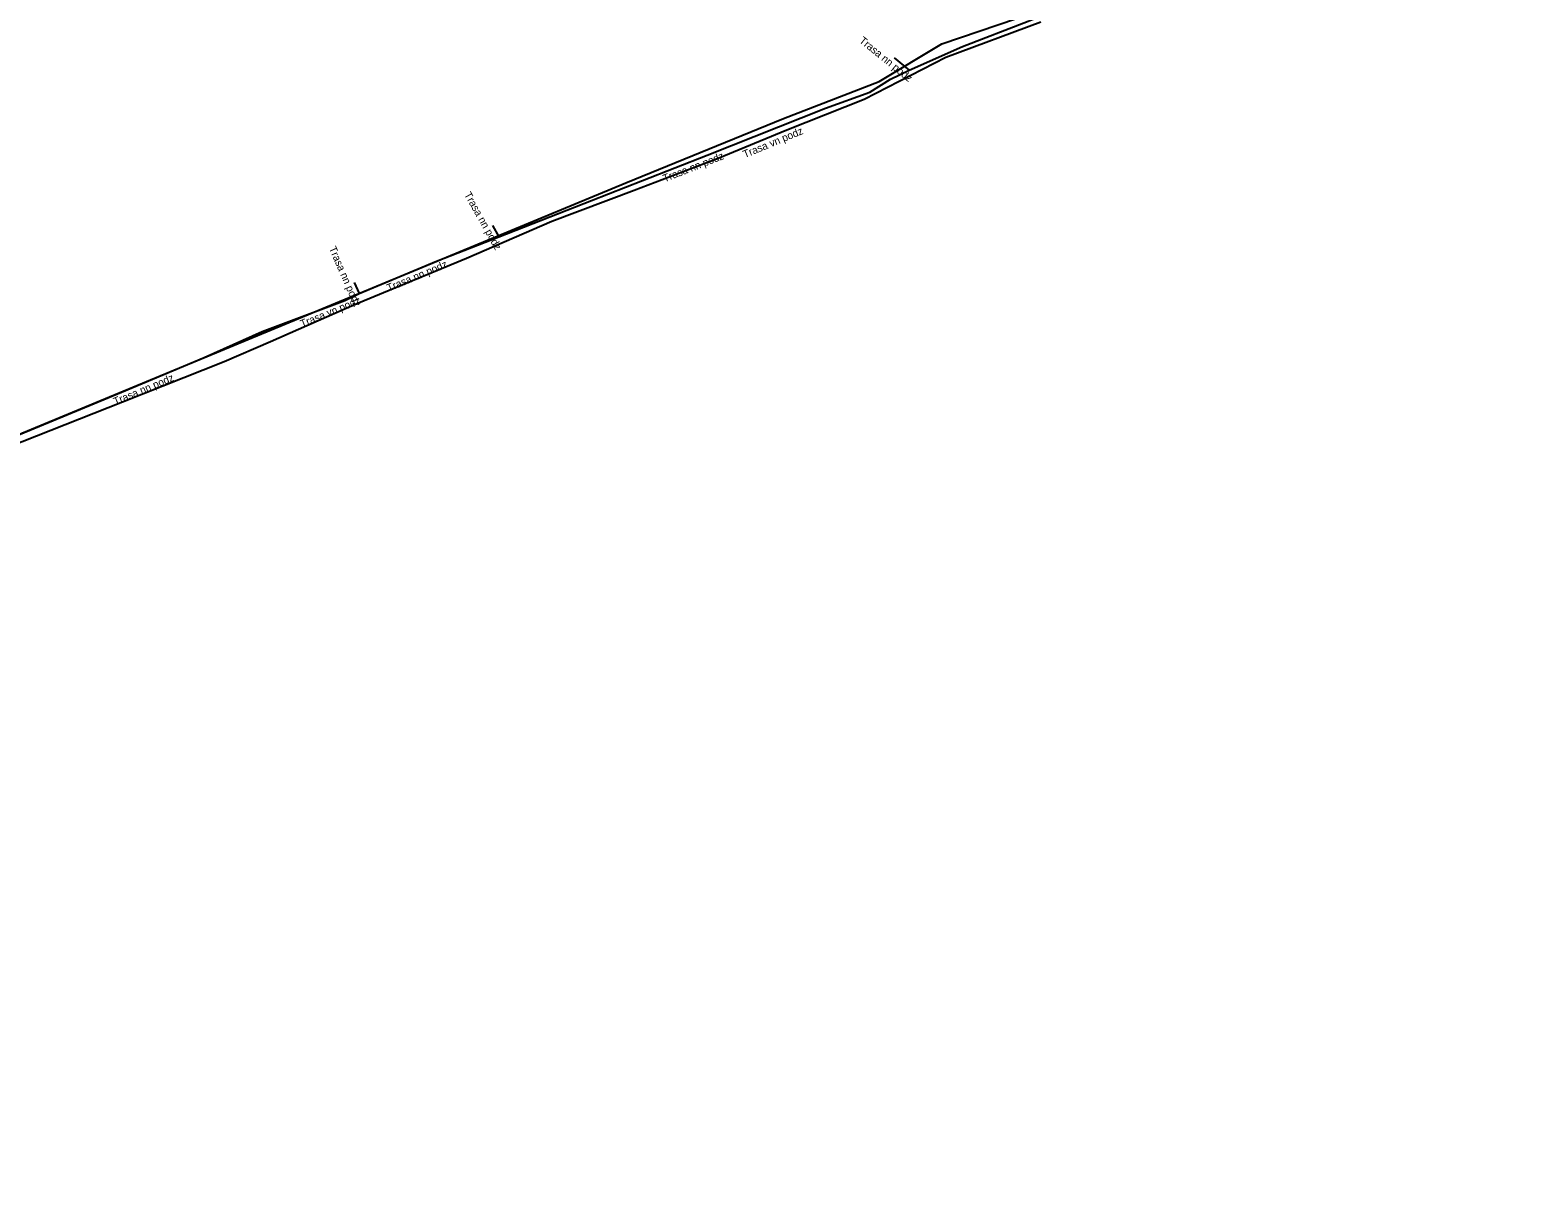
# Model space of a CAD drawing. Extents: x -756855 to -756032, y -1046964 to -1046550.
# Drawn here: x -756275 to -756176.1, y -1046755.6 to -1046678 of the extents above; entities that cross this region are included whole.
import ezdxf

# ---------------------------------------------------------------- set-up
doc = ezdxf.new("R2010")
doc.units = 0
for name, color, linetype in [('Popiskový text - Ostatní atributy Trasy', 7, 'Continuous'), ('Spojnice NN', 7, 'Continuous'), ('Spojnice VN', 7, 'Continuous')]:
    doc.layers.add(name, color=color, linetype=linetype)

msp = doc.modelspace()

# ---------------------------------------------------------------- linework, layer by layer
at = {"layer": 'Spojnice NN'}
for points in [[(-756216.68, -1046680.63), (-756213.14, -1046679.07), (-756208.8, -1046677.38), (-756202.39, -1046674.81), (-756199.33, -1046673.47), (-756198.53, -1046673.21), (-756193.13, -1046671.3)], [(-756217.68, -1046679.82), (-756216.68, -1046680.63)], [(-756243.88, -1046691.67), (-756237.73, -1046689.27), (-756234.35, -1046687.93), (-756230.08, -1046686.26), (-756222.22, -1046683.15), (-756219.28, -1046682.09), (-756217.93, -1046681.23), (-756216.68, -1046680.63)], [(-756253.15, -1046695.43), (-756248.01, -1046693.28), (-756243.88, -1046691.67)], [(-756244.3, -1046690.92), (-756243.88, -1046691.67)], [(-756280.16, -1046706.63), (-756279.11, -1046706.17), (-756273.42, -1046703.85), (-756268.9, -1046701.96), (-756263.42, -1046699.66), (-756259.58, -1046697.94), (-756254.1, -1046695.88), (-756253.15, -1046695.43)], [(-756253.47, -1046694.69), (-756253.15, -1046695.43)]]:
    msp.add_lwpolyline(points, dxfattribs=at)
at = {"layer": 'Spojnice VN'}
for points in [[(-756313.81, -1046744.85), (-756314.068, -1046743.84), (-756320.841, -1046722.839), (-756309.759, -1046718.776), (-756280.687, -1046706.831), (-756235.46, -1046688.092), (-756225.019, -1046683.824), (-756218.665, -1046681.386), (-756214.528, -1046678.874), (-756204.554, -1046675.475), (-756195.393, -1046671.782), (-756193.62, -1046671.264), (-756177.335, -1046664.123), (-756176.05, -1046663.022), (-756176.718, -1046658.811), (-756178.085, -1046656.232), (-756180.465, -1046655.28), (-756180.553, -1046655.28), (-756180.638, -1046655.313)], [(-756207.955, -1046677.449), (-756214.262, -1046679.793), (-756219.673, -1046682.574), (-756224.783, -1046684.597), (-756229.34, -1046686.483), (-756234.91, -1046688.598), (-756240.37, -1046690.65), (-756246.034, -1046693.104), (-756253.445, -1046696.185), (-756259.015, -1046698.622), (-756262.099, -1046699.955), (-756268.82, -1046702.622), (-756278.36, -1046706.37), (-756286.84, -1046710.127), (-756292.64, -1046712.427), (-756302.4, -1046716.01), (-756310.853, -1046719.83), (-756319.001, -1046723.14), (-756322.108, -1046723.922), (-756361.458, -1046740.553), (-756398.245, -1046755.557)]]:
    msp.add_lwpolyline(points, dxfattribs=at)

# ---------------------------------------------------------------- texts
at = {"layer": 'Popiskový text - Ostatní atributy Trasy'}
for s, rotation, p in [('Trasa nn podz', 320.99253, (-756220.035, -1046678.749)), ('Trasa vn podz', 22.48314, (-756227.578, -1046686.458)), ('Trasa nn podz', 21.3605, (-756232.894, -1046688.058)), ('Trasa nn podz', 299.24883, (-756246.195, -1046688.866)), ('Trasa nn podz', 293.38522, (-756255.156, -1046692.429)), ('Trasa nn podz', 22.69897, (-756251.188, -1046695.314)), ('Trasa vn podz', 22.5058, (-756256.924, -1046697.689)), ('Trasa nn podz', 22.76818, (-756269.308, -1046702.836))]:
    msp.add_text(s, height=0.5, rotation=rotation, dxfattribs=at).set_placement(p)

doc.saveas('drawing.dxf')
